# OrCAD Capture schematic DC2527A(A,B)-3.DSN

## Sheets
1 PAGE2: size Custom; title: HIGH EFFICIENCY, DUAL 15A  STEP-DOWN       MODULE REGULATOR; rev: 3; company: TM
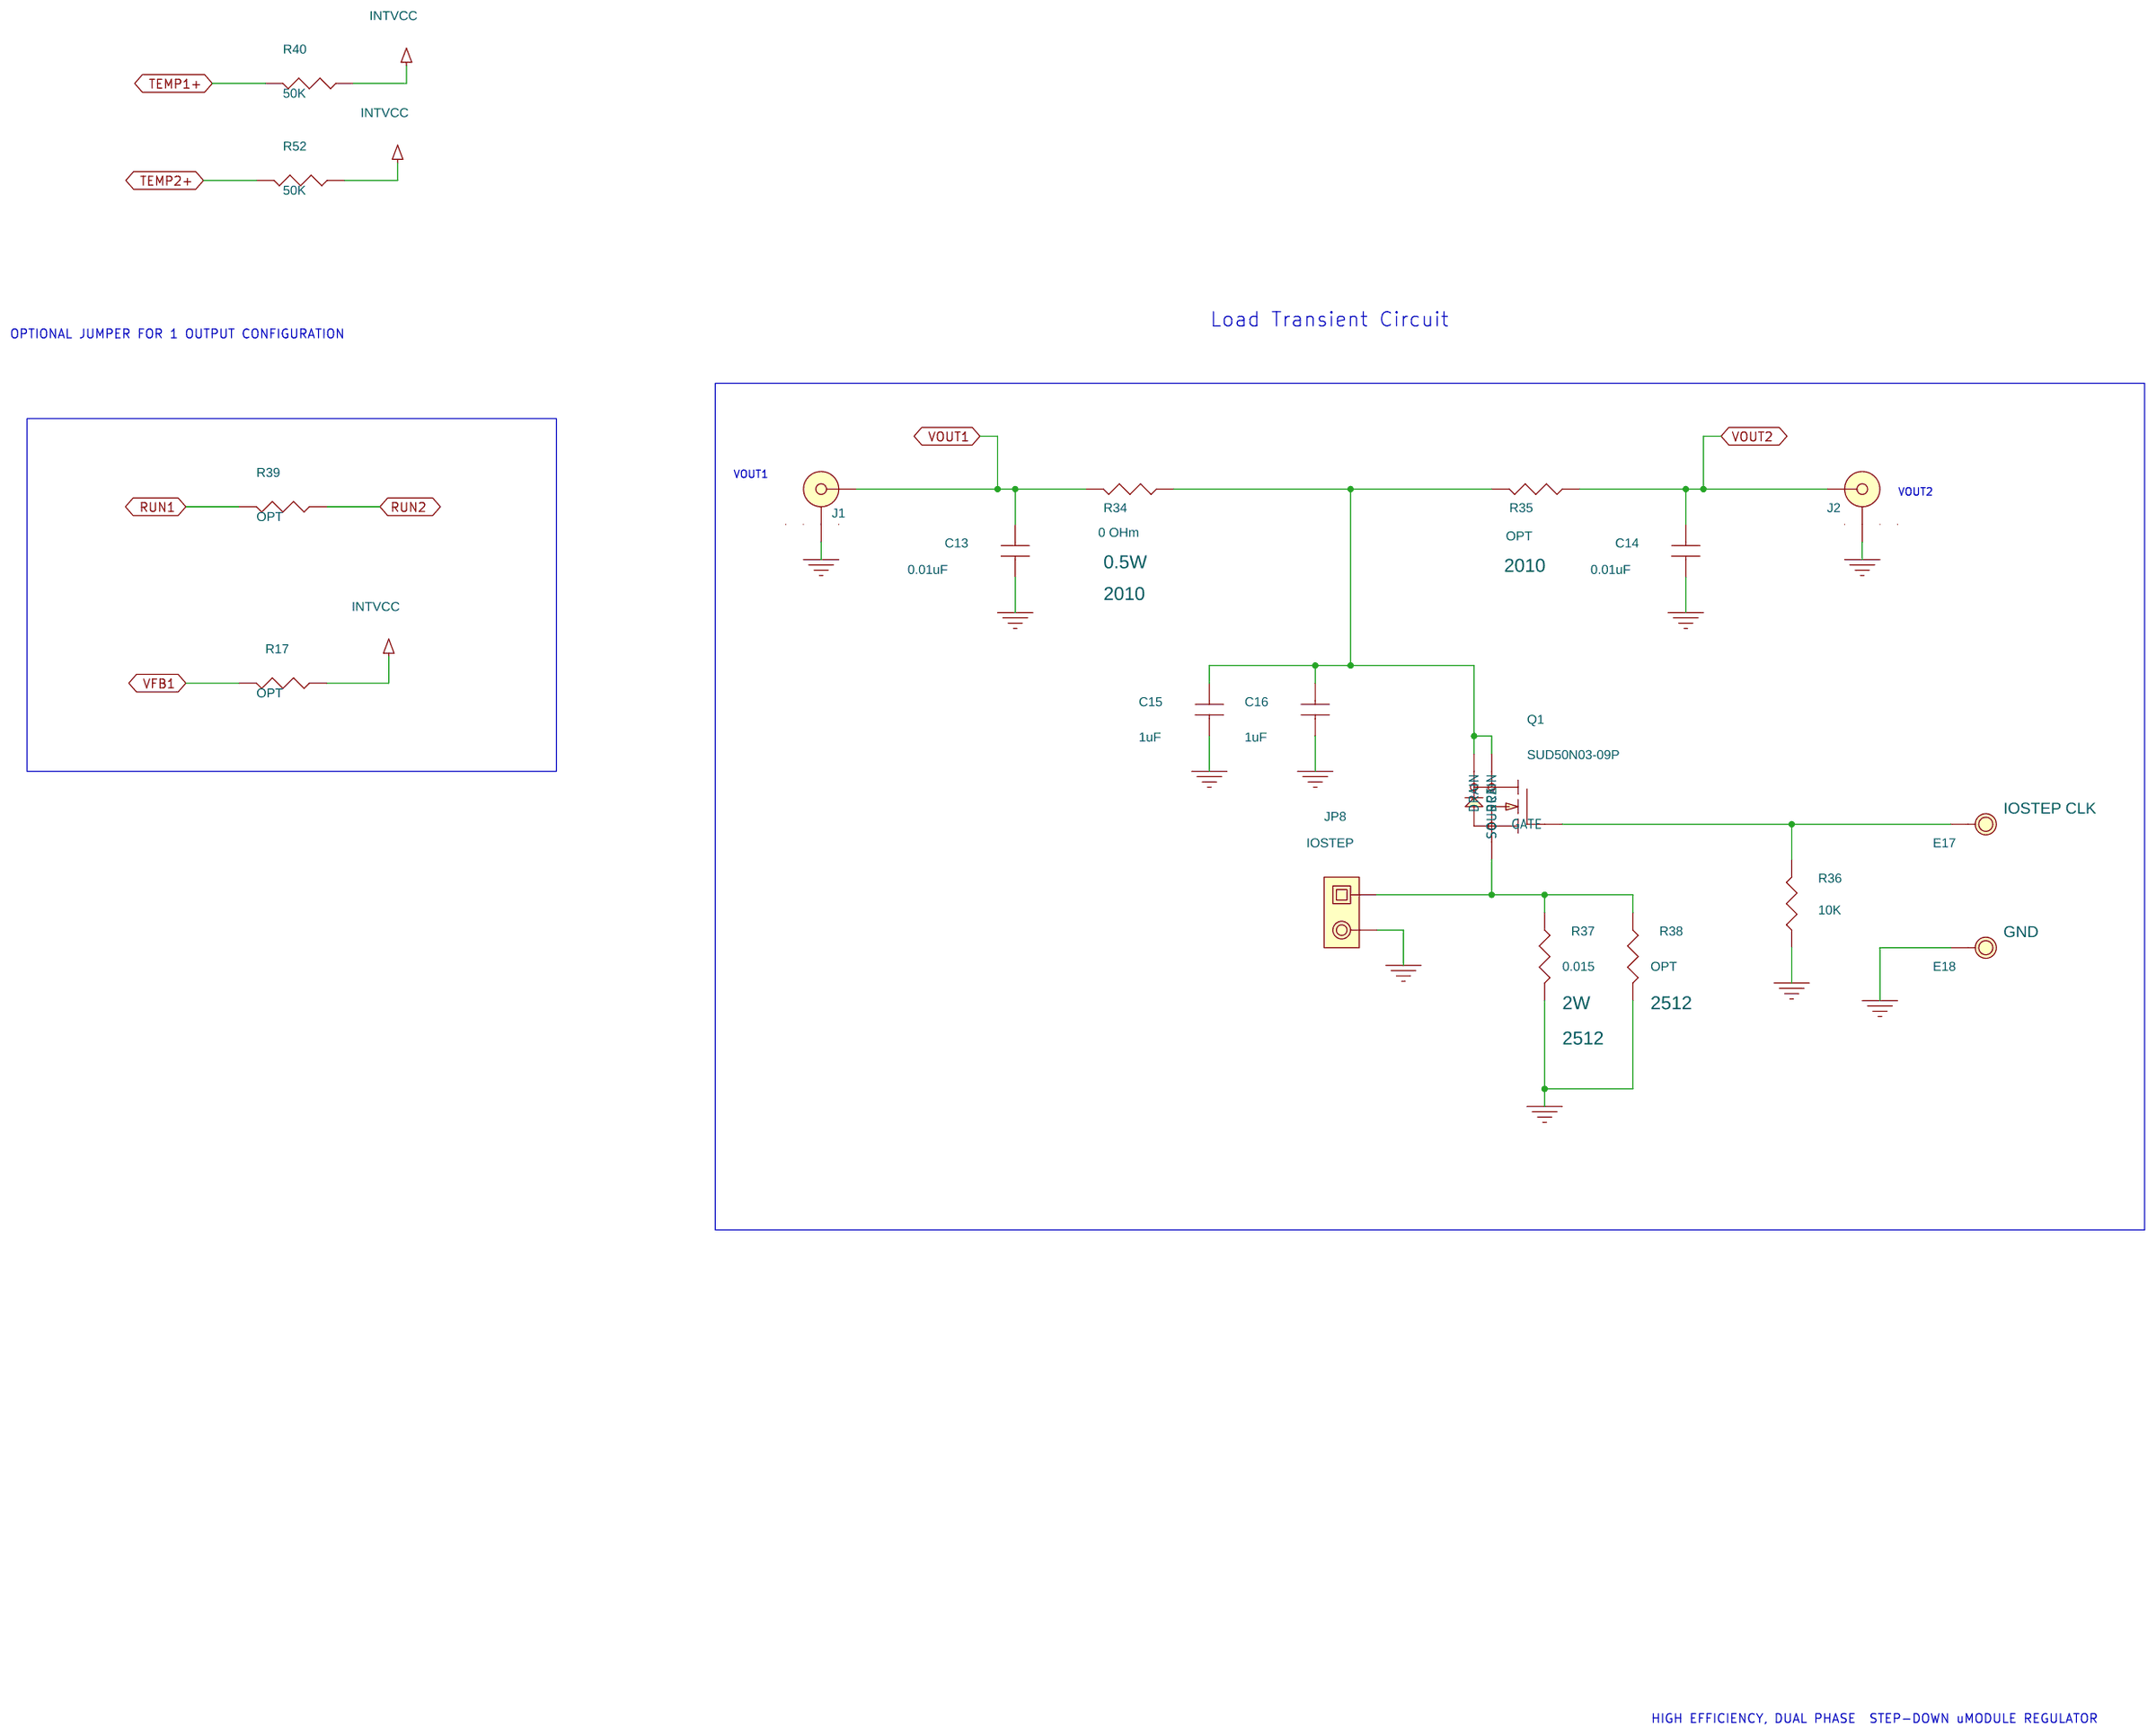
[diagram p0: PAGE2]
2 LTM4662/4646EY: size Custom
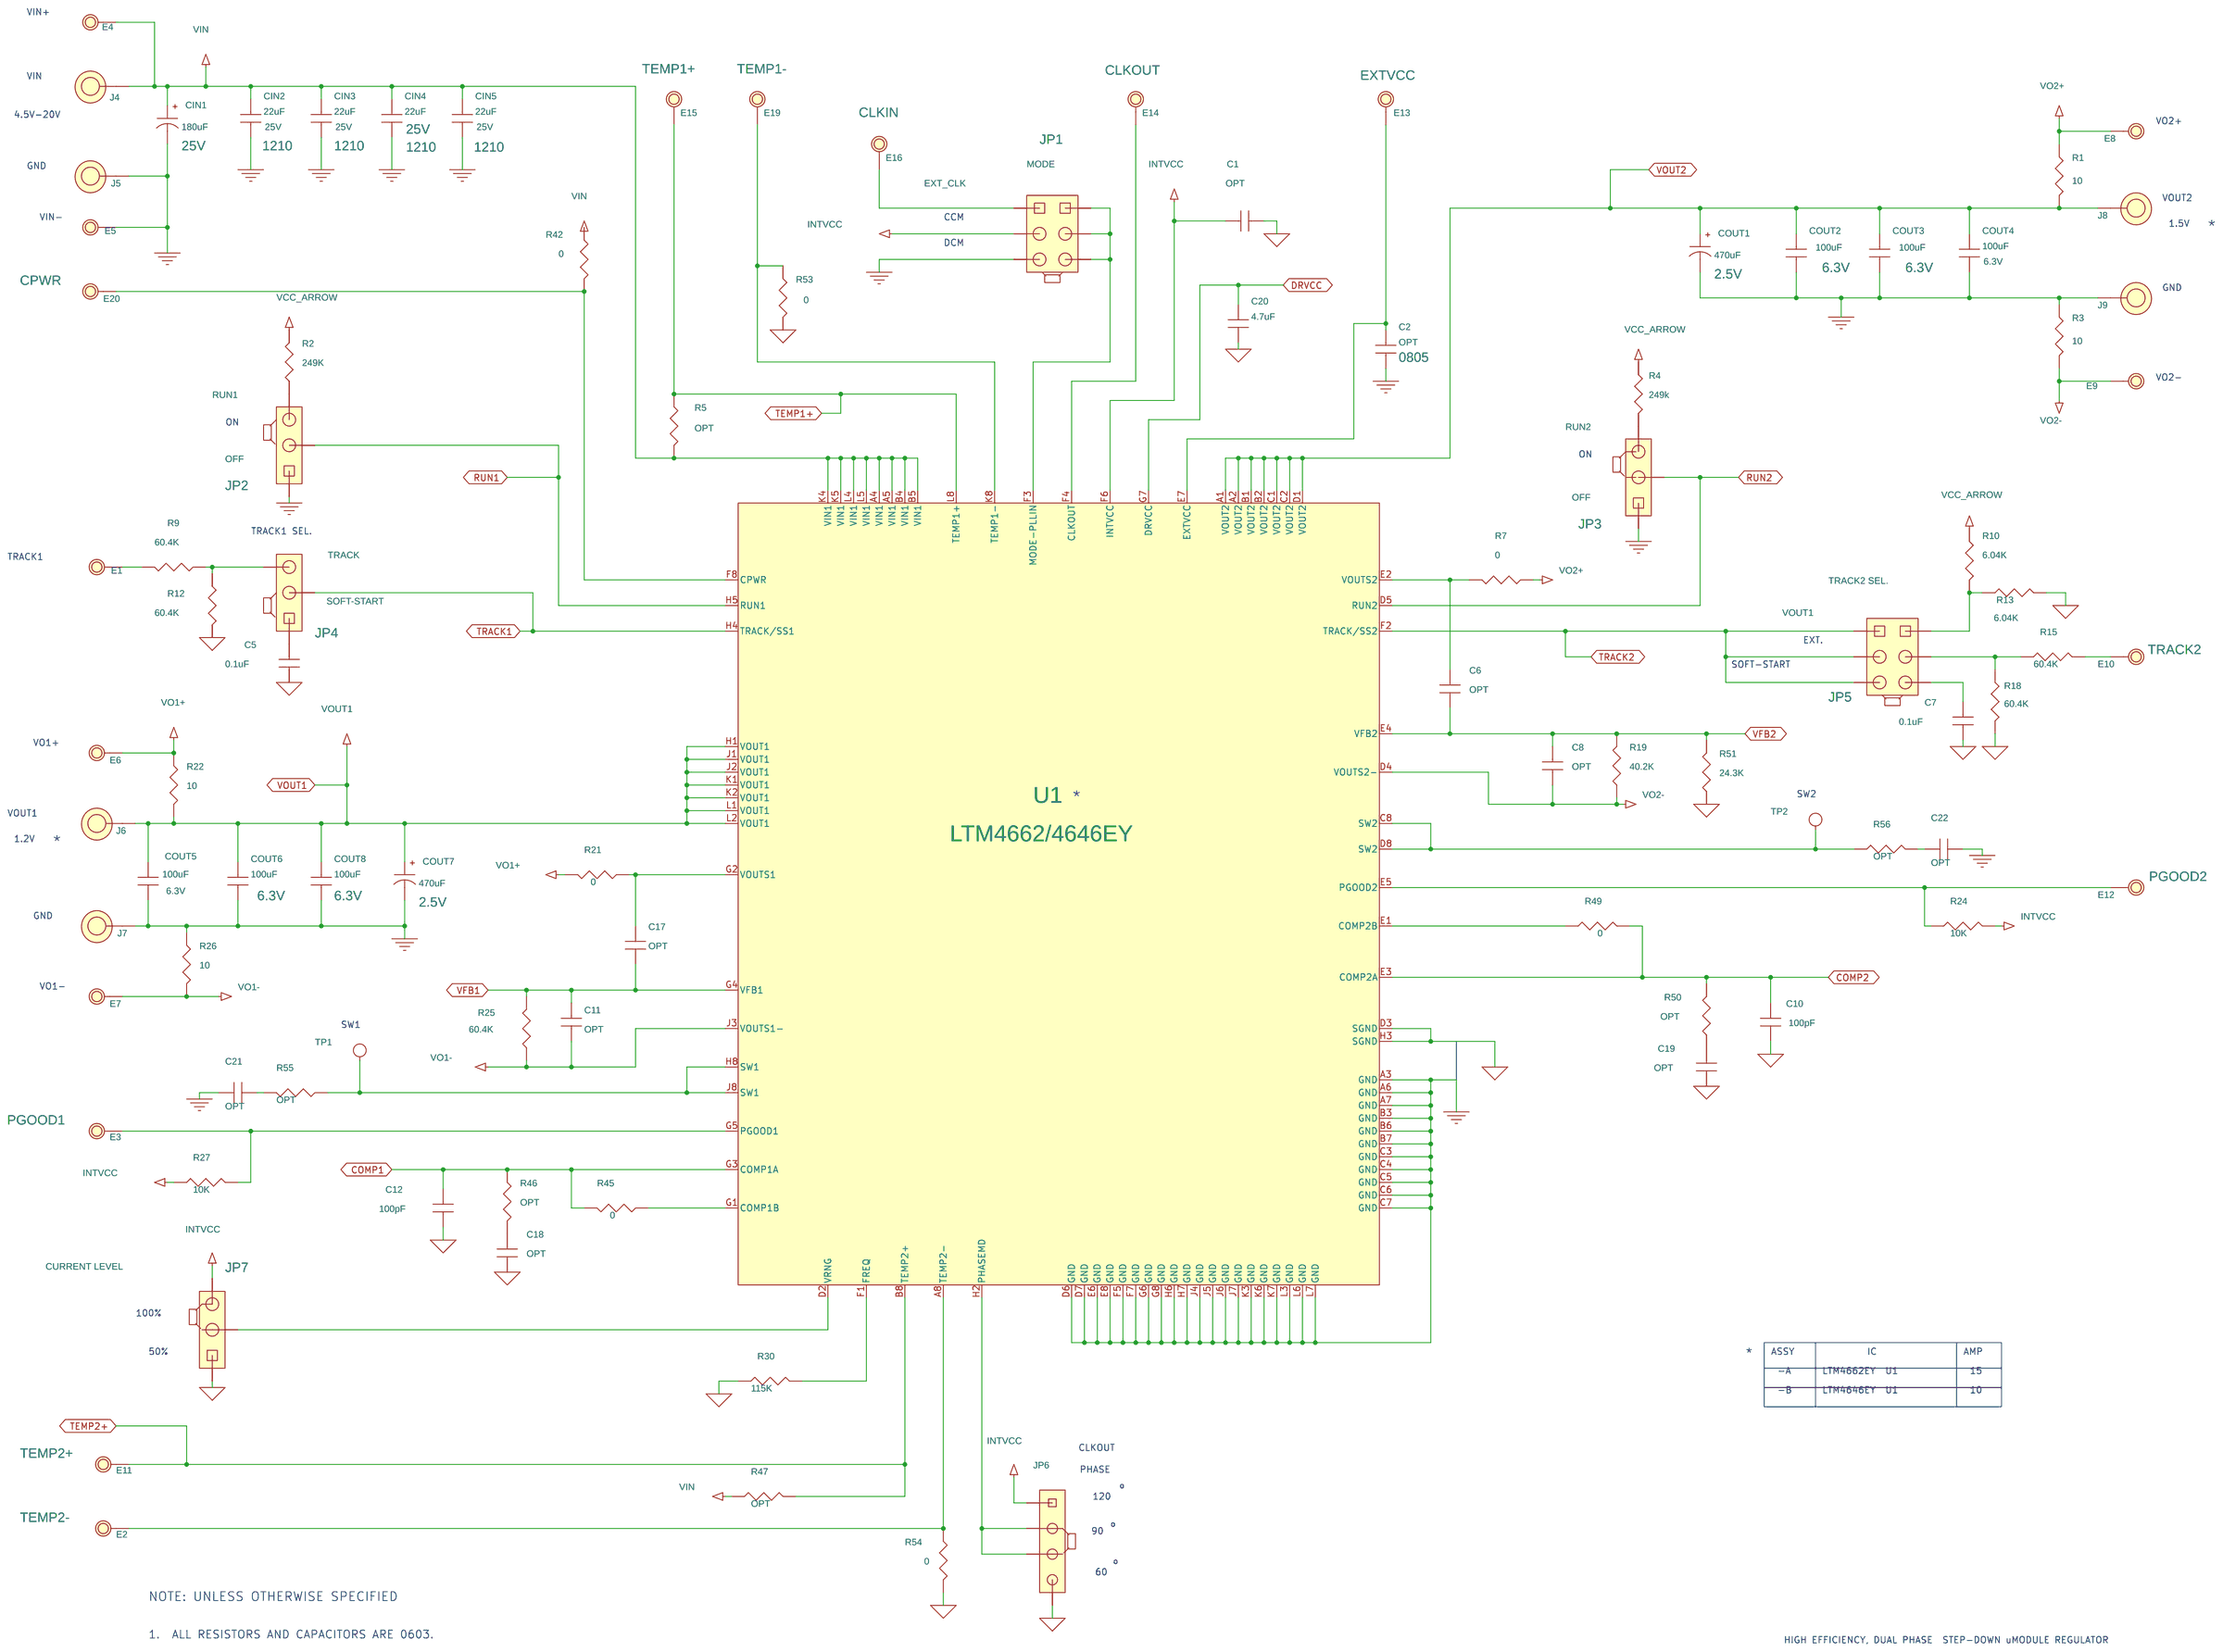
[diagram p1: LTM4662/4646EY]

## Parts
sheet LTM4662/4646EY
C1  OPT  [0805]
C2  OPT  [0805]
C5  0.1uF  [0603]
C6  OPT  [0603]
C7  0.1uF  [0603]
C8  OPT  [0603]
C10  100pF  [0603]
C11  OPT  [0603]
C12  100pF  [0603]
C17  OPT  [0603]
C18  OPT  [0603]
C19  OPT  [0603]
C20  4.7uF  [0603]
C21  OPT  [0603]
C22  OPT  [0603]
CIN1  180uF  [CAP-8.0]
CIN2  22uF  [1210]
CIN3  22uF  [1210]
CIN4  22uF  [1210]
CIN5  22uF  [1210]
COUT1  470uF  [SANYO-D4D]
COUT2  100uF  [1210]
COUT3  100uF  [1210]
COUT4  100uF  [1210]
COUT5  100uF  [1210]
COUT6  100uF  [1210]
COUT7  470uF  [SANYO-D4D]
COUT8  100uF  [1210]
E1  Testpoint  [MM/2501]
E2  TEMP2-  [MM/2501]
E3  PGOOD1  [MM/2501]
E4  Testpoint  [MM/2501]
E5  Testpoint  [MM/2501]
E6  Testpoint  [MM/2501]
E7  Testpoint  [MM/2501]
E8  Testpoint  [MM/2501]
E9  Testpoint  [MM/2501]
E10  TRACK2  [MM/2501]
E11  TEMP2+  [MM/2501]
E12  PGOOD2  [MM/2501]
E13  EXTVCC  [MM/2501]
E14  CLKOUT  [MM/2501]
E15  TEMP1+  [MM/2501]
E16  CLKIN  [MM/2501]
E19  TEMP1-  [MM/2501]
E20  CPWR  [MM/2501]
J4  KEY-575--4  [KEY-575-4]
J5  KEY-575--4  [KEY-575-4]
J6  KEY-575--4  [KEY-575-4]
J7  KEY-575--4  [KEY-575-4]
J8  KEY-575--4  [KEY-575-4]
J9  KEY-575--4  [KEY-575-4]
JP1  HDR2X3  [HEADER3X2-0.79]
JP2  HDR1X3  [commcon2802s03g2]
JP3  HDR1X3  [commcon2802s03g2]
JP4  HDR1X3  [commcon2802s03g2]
JP5  HDR2X3  [HEADER3X2-0.79]
JP6  HDR1X4  [jumper4pin-79mil]
JP7  HDR1X3  [commcon2802s03g2]
R1  10  [0603]
R2  249K  [0603]
R3  10  [0603]
R4  249k  [0603]
R5  OPT  [0603]
R7  0  [0603]
R9  60.4K  [0603]
R10  6.04K  [0603]
R12  60.4K  [0603]
R13  6.04K  [0603]
R15  60.4K  [0603]
R18  60.4K  [0603]
R19  40.2K  [0603]
R21  0  [0603]
R22  10  [0603]
R24  10K  [0603]
R25  60.4K  [0603]
R26  10  [0603]
R27  10K  [0603]
R30  115K  [0603]
R42  0  [0603]
R45  0  [0603]
R46  OPT  [0603]
R47  OPT  [0603]
R49  0  [0603]
R50  OPT  [0603]
R51  24.3K  [0603]
R53  0  [0603]
R54  0  [0603]
R55  OPT  [0603]
R56  OPT  [0603]
TP1  SM/TP  [SM/TP]
TP2  SM/TP  [SM/TP]
U1  LTM4662/4646EY  [BGA88-15X11.25-6.01]
XJP1  2mm Ctrs.
XJP2  2mm Ctrs.
XJP3  2mm Ctrs.
XJP4  2mm Ctrs.
XJP5  2mm Ctrs.
XJP6  2mm Ctrs.
XJP7  2mm Ctrs.
sheet PAGE2
C13  0.01uF  [0603]
C14  0.01uF  [0603]
C15  1uF  [0603]
C16  1uF  [0603]
E17  IOSTEP CLK  [MM/2501]
E18  GND  [MM/2501]
J1  CON-SMA-EDGE  [BNC5]
J2  CON-SMA-EDGE  [BNC5]
JP8  HD1X2-079  [HD1X2-079]
Q1  SUD50N03-09P  [TO252]
R17  OPT  [0603]
R34  0 OHm  [2010]
R35  OPT  [2010]
R36  10K  [0603]
R37  0.015  [2512]
R38  OPT  [2512]
R39  OPT  [0603]
R40  50K  [0603]
R52  50K  [0603]

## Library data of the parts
C1 C2 C5 C7 C17 C20-C22 CIN2-CIN5 = CAP1206: 1ST PART FIELD: 25V; 2ND PART FIELD: 0805-1206
C6 C8 C10-C12 C18 C19 COUT4 = CAP1206: 1ST PART FIELD: 6.3V; 2ND PART FIELD: 0805-1206
CIN1 = CAP-SVPA-E7: 1ST PART FIELD: 25V
COUT1 COUT7 = CAP-SVPA-E7: 1ST PART FIELD: 2.5V
COUT2 COUT3 = CAP1206: 1ST PART FIELD: 25V; 2ND PART FIELD: 0805-1206; VOLTAGE: 6.3V
COUT5 = CAP1210: 1ST PART FIELD: 6.3V; 2ND PART FIELD: 1210-3743
COUT6 COUT8 = CAP1206: 1ST PART FIELD: 6.3V; 2ND PART FIELD: 0805-1206; VOLTAGE: 6.3V
E1-E20 = MillMax-2501
J4-J9 = KEY-575--4_1
JP1 = Commcon2802s03g2_4: 11th Part Field: EXT_CLK; 12th Part Field: MODE; 9th Part Field: ON
JP2 = Commcon2802s03g2_1: 11th Part Field: OFF; 12th Part Field: RUN1; 9th Part Field: ON
JP3 = Commcon2802s03g2_1: 11th Part Field: OFF; 12th Part Field: RUN2; 9th Part Field: ON
JP4 = Commcon2802s03g2_2: 11th Part Field: SOFT-START; 12th Part Field: TRACK; 9th Part Field: ON
JP5 = Commcon2802s03g2_4: 11th Part Field: VOUT1; 12th Part Field: TRACK2 SEL.; 9th Part Field: ON
JP6 = Commcon2802s03g2_5: 11th Part Field: OFF; 12th Part Field: RUN; 9th Part Field: ON
JP7 = Commcon2802s03g2_1: 11th Part Field: 15A; 12th Part Field: CURRENT LEVEL; 9th Part Field: ON
R1-R5 R7 R9 R10 R12 R13 R15 R17-R19 R21 R22 R24-R27 R30 R36 R39 R40 R42 R45-R47 R49-R56 = AAC-0603
TP1 TP2 = E-100SMT
U1 = LTM4662_4646EY
XJP1-XJP7 = CommconCCIJ2MM-138G
C13-C16 = CAP0402
J1 J2 = CON-SMA-EDGE_0
JP8 = HD1X2: 10th Part Field: OFF; 12th Part Field: IOSTEP; 9th Part Field: ON
Q1 = IRF540_0
R34 R35 = AAC-0603: 1ST PART FIELD: 0.5W
R37 R38 = AAC-0603: 1ST PART FIELD: 2W

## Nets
GND: C2.2 C13.2 C14.2 C15.2 C16.2 C21.1 C22.1 CIN1.2 CIN2.2 CIN3.2 CIN4.2 CIN5.2 COUT1.2 COUT2.2 COUT3.2 COUT4.2 COUT5.2 COUT6.2 COUT7.2 COUT8.2 E5.1 E18.1 J1.2(GND) J1.3 J1.4(GND) J1.5(GND) J2.2(GND) J2.3 J2.4(GND) J2.5(GND) J5.1 J7.1 J9.1 JP1.5 JP2.1 JP3.1 JP8.2 R3.1 R26.1 R36.1 R37.2 R38.2 U1.A3(GND) U1.A6(GND) U1.A7(GND) U1.B3(GND) U1.B6(GND) U1.B7(GND) U1.C3(GND) U1.C4(GND) U1.C5(GND) U1.C6(GND) U1.C7(GND) U1.D6(GND) U1.D7(GND) U1.E6(GND) U1.E8(GND) U1.F5(GND) U1.F7(GND) U1.G6(GND) U1.G8(GND) U1.H6(GND) U1.H7(GND) U1.J4(GND) U1.J5(GND) U1.J6(GND) U1.J7(GND) U1.K3(GND) U1.K6(GND) U1.K7(GND) U1.L3(GND) U1.L6(GND) U1.L7(GND)
GND_SIGNAL: C1.2 C5.2 C7.2 C10.2 C12.2 C18.2 C19.2 C20.2 JP6.4 JP7.1 R12.2 R13.2 R18.2 R30.1 R51.1 R53.2 R54.2 U1.D3(SGND) U1.H3(SGND)
VIN: CIN1.1 CIN2.1 CIN3.1 CIN4.1 CIN5.1 E4.1 J4.1 R2.2 R4.2 R5.2 R42.1 R47.1 U1.A4(VIN1) U1.A5(VIN1) U1.B4(VIN1) U1.B5(VIN1) U1.K4(VIN1) U1.K5(VIN1) U1.L4(VIN1) U1.L5(VIN1)
COMP1: C12.1 R45.2 R46.1 U1.G3(COMP1A)
COMP2: C10.1 R49.2 R50.1 U1.E3(COMP2A)
DRVCC: C20.1 U1.G7(DRVCC)
INTVCC: C1.1 JP1.3 JP6.1 JP7.3 R17.1 R24.2 R27.1 R40.1 R52.1 U1.F6(INTVCC)
RUN1: JP2.2 R39.2 U1.H5(RUN1)
RUN2: JP3.2 R39.1 U1.D5(RUN2)
TEMP1+: E15.1 R5.1 R40.2 U1.L8(TEMP1+)
TEMP2+: E11.1 R47.2 R52.2 U1.B8(TEMP2+)
TRACK1: JP4.2 U1.H4(TRACK/SS1)
TRACK2: JP5.1 JP5.3 JP5.5 U1.F2(TRACK/SS2)
VFB1: C11.1 C17.2 R17.2 R25.2 U1.G4(VFB1)
VFB2: C6.2 C8.1 R19.2 R51.2 U1.E4(VFB2)
VO1+: E6.1 R21.2 R22.1
VO1-: C11.2 E7.1 R25.1 R26.2 U1.J3(VOUTS1-)
VO2+: E8.1 R1.1 R7.1
VO2-: C8.2 E9.1 R3.2 R19.1 U1.D4(VOUTS2-)
VOUT1: C13.1 COUT5.1 COUT6.1 COUT7.1 COUT8.1 J1.1 J6.1 R10.1 R22.2 R34.2 U1.H1(VOUT1) U1.J1(VOUT1) U1.J2(VOUT1) U1.K1(VOUT1) U1.K2(VOUT1) U1.L1(VOUT1) U1.L2(VOUT1)
VOUT2: C14.1 COUT1.1 COUT2.1 COUT3.1 COUT4.1 J2.1 J8.1 R1.2 R35.1 U1.A1(VOUT2) U1.A2(VOUT2) U1.B1(VOUT2) U1.B2(VOUT2) U1.C1(VOUT2) U1.C2(VOUT2) U1.D1(VOUT2)
N295820: JP1.2 JP1.4 JP1.6 U1.F3(MODE-PLLIN)
N296492: E14.1 U1.F4(CLKOUT)
N304050: C6.1 R7.2 U1.E2(VOUTS2)
N343284: JP4.3 R9.1 R12.1
N343594: E1.1 R9.2
N356855: E3.1 R27.2 U1.G5(PGOOD1)
N375571: JP5.2 R10.2 R13.1
N375697: JP5.4 R15.1 R18.1
N375732: C7.1 JP5.6
N413641: E12.1 R24.1 U1.E5(PGOOD2)
N441126: C2.1 E13.1 U1.E7(EXTVCC)
N484927: E10.1 R15.2
N1254513: C15.1 C16.1 Q1.2(DRAIN) Q1.4(DRAIN) R34.1 R35.2
N1255019: E17.1 Q1.1(GATE) R36.2
N1255527: JP8.1 Q1.3(SOURCE) R37.1 R38.1
N1335366: R56.1 TP2.1(A) U1.C8(SW2) U1.D8(SW2)
N16626750: E16.1 JP1.1
N16818274: E19.1 R53.1 U1.K8(TEMP1-)
N16822417: E20.1 R42.2 U1.F8(CPWR)
N16829322: C17.1 R21.1 U1.G2(VOUTS1)
N16830711: R55.1 TP1.1(A) U1.H8(SW1) U1.J8(SW1)
N16831093: R45.1 U1.G1(COMP1B)
N16832825: JP7.2 U1.D2(VRNG)
N16834216: R30.2 U1.F1(FREQ)
N16834844: E2.1 R54.1 U1.A8(TEMP2-)
N16836650: JP6.2 JP6.3 U1.H2(PHASEMD)
N16843619: R49.1 U1.E1(COMP2B)
N16868918: C21.2 R55.2
N16869488: C22.2 R56.2
N16879352: C5.1 JP4.1
N16879353: JP2.3 R2.1
N16879354: C18.1 R46.2
N16879357: C19.1 R50.2
N16879360: JP3.3 R4.1

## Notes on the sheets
sheet 1
- Load Transient Circuit
- OPTIONAL JUMPER FOR 1 OUTPUT CONFIGURATION
- VOUT1
- VOUT2
- HIGH EFFICIENCY, DUAL PHASE  STEP-DOWN uMODULE REGULATOR
sheet 2
- VIN+
- VIN
- 4.5V-20V
- VO2+
- GND
- VOUT2
- VIN-
- CCM
- 1.5V
- *
- DCM
- GND
- VO2-
- ON
- ON
- TRACK1 SEL.
- TRACK1
- EXT.
- SOFT-START
- VO1+
- *
- SW2
- VOUT1
- 1.2V
- *
- GND
- VO1-
- SW1
- 100%
- 50%
- *
- ASSY
- IC
- AMP
- -A
- LTM4662EY  U1
- 15
- -B
- LTM4646EY  U1
- 10
- CLKOUT
- PHASE
- o
- 120
- o
- 90
- o
- 60
- NOTE: UNLESS OTHERWISE SPECIFIED
- 1.  ALL RESISTORS AND CAPACITORS ARE 0603.
- HIGH EFFICIENCY, DUAL PHASE  STEP-DOWN uMODULE REGULATOR
